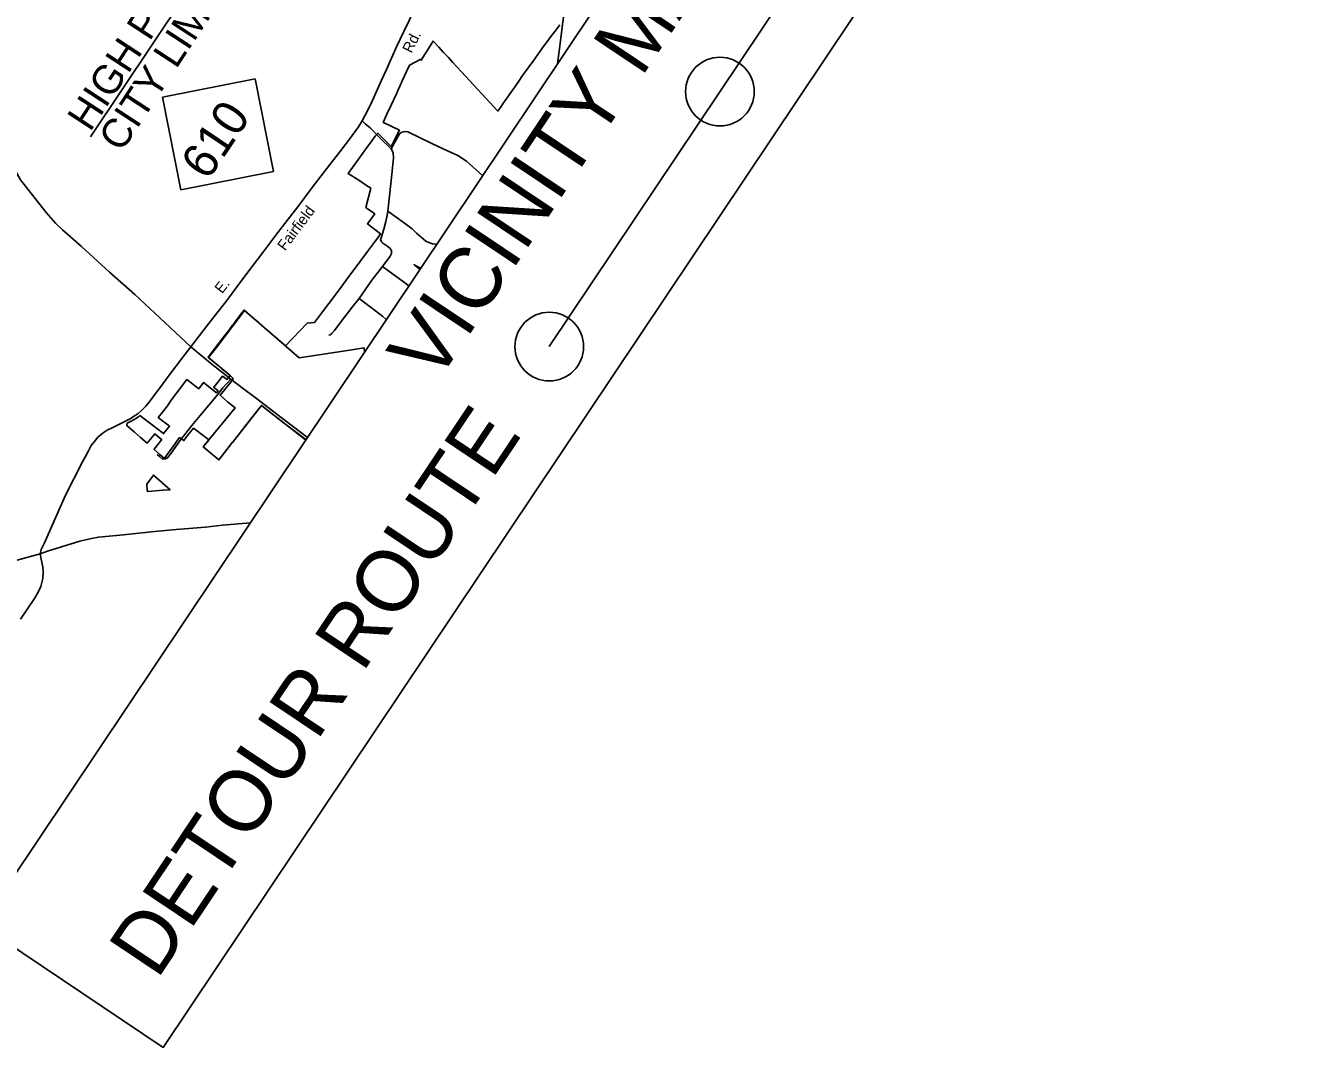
# Model space of a CAD drawing. Extents: x 1716282 to 1717158, y 799307 to 801078.
# Drawn here: x 1716655.2 to 1716967.1, y 800387.2 to 800636.9 of the extents above; entities that cross this region are included whole.
import ezdxf

# ---------------------------------------------------------------- set-up
doc = ezdxf.new("R2010")
doc.units = 0
for name, color, linetype in [('Exist Boundary Political City Limit New', 7, 'Continuous'), ('Exist Road Primary NC Attributed', 7, 'Continuous'), ('Exist Road Primary NC Label', 7, 'Continuous'), ('Exist Road Primary US UnDivided 4 Lane Attributed', 7, 'Continuous'), ('Exist Road Secondary Type 51 Attributed', 7, 'Continuous'), ('Map Preparation Boundary City Limit Buffer Line', 7, 'Continuous'), ('Old_Level_2', 7, 'Continuous'), ('Prop DSN Text', 7, 'Continuous')]:
    doc.layers.add(name, color=color, linetype=linetype)

msp = doc.modelspace()

# ---------------------------------------------------------------- linework, layer by layer
at = {"layer": 'Exist Boundary Political City Limit New'}
for points in [[(1716699.94, 800555.77), (1716699.83, 800555.86), (1716702.5, 800559.29), (1716703.08, 800560.05), (1716703.88, 800561.08), (1716704.85, 800562.33), (1716705.08, 800562.62), (1716705.85, 800563.67), (1716705.87, 800563.7), (1716707.14, 800565.38), (1716708.13, 800566.7), (1716708.65, 800567.4), (1716709.47, 800566.68), (1716710.49, 800565.8), (1716711.12, 800565.25), (1716712.01, 800564.49), (1716712.14, 800564.37), (1716712.3, 800564.24), (1716712.84, 800563.77), (1716713.66, 800563.06), (1716714.62, 800562.23), (1716715.44, 800561.52), (1716716.34, 800560.74), (1716718.23, 800559.11), (1716718.73, 800558.67), (1716724.09, 800564.21), (1716725.89, 800564.36), (1716727.8, 800566.92), (1716729.36, 800569.01), (1716730.63, 800570.72), (1716732.5, 800573.22), (1716734.02, 800575.26), (1716735.55, 800577.31), (1716738.85, 800581.74), (1716740.74, 800584.29), (1716741.31, 800585.07), (1716741.95, 800586.02), (1716738.81, 800588.44), (1716740.59, 800590.88), (1716739.7, 800591.53), (1716738.85, 800592.14), (1716738.42, 800592.46), (1716739.59, 800597.21), (1716739.26, 800597.43), (1716738.84, 800597.71), (1716736.92, 800598.95), (1716734.07, 800600.78), (1716735.54, 800602.81), (1716737.66, 800605.74), (1716738.93, 800607.48), (1716739.45, 800608.21), (1716740.71, 800609.92), (1716741.31, 800610.6), (1716744.62, 800607.4), (1716746.6, 800611.36), (1716742.71, 800613.22), (1716742.64, 800613.26), (1716743.55, 800615.24), (1716744.49, 800617.3), (1716745.86, 800620.27), (1716746.28, 800621.18), (1716746.77, 800622.25), (1716747.39, 800623.57), (1716747.87, 800624.61), (1716748.36, 800625.68), (1716749.07, 800627.21), (1716751.83, 800628.69), (1716751.94, 800628.47), (1716754.84, 800633.13), (1716756.22, 800631.64), (1716757.38, 800630.38), (1716758.57, 800629.1), (1716759.67, 800627.9), (1716760.76, 800626.72), (1716761.77, 800625.63), (1716770.65, 800616.01), (1716771.47, 800617.17), (1716771.89, 800617.77), (1716773.83, 800620.53), (1716774.46, 800621.43), (1716774.89, 800622.05), (1716775.93, 800623.57), (1716776.54, 800624.5), (1716776.94, 800625.06), (1716779.44, 800628.51), (1716781.61, 800631.51), (1716783.22, 800633.72), (1716783.89, 800634.6), (1716784.64, 800635.58), (1716785.58, 800636.8), (1716785.85, 800637.14)], [(1716751.75, 800577.61), (1716750.19, 800578.47), (1716751.6, 800577.38)], [(1716738.04, 800557.12), (1716737.99, 800558.13), (1716733.91, 800557.53), (1716722.1, 800555.73), (1716717.13, 800560.02), (1716708.72, 800567.3), (1716705.95, 800563.6), (1716701.87, 800558.28), (1716699.94, 800555.77)], [(1716699.94, 800555.77), (1716705.23, 800551.42), (1716706.01, 800550.66), (1716705.39, 800549.77), (1716703.17, 800547.06), (1716702.78, 800546.59), (1716704.57, 800544.99), (1716706.45, 800543.51), (1716700.04, 800535.64), (1716698.65, 800533.94), (1716702.48, 800530.78), (1716705.8, 800535.08), (1716705.83, 800535.05), (1716712.88, 800544.08), (1716723.69, 800535.68)], [(1716705.23, 800551.42), (1716703.33, 800552.96), (1716703.19, 800553.08), (1716701.52, 800554.48), (1716700.68, 800555.17), (1716700.06, 800555.68), (1716699.94, 800555.77)], [(1716700.04, 800535.64), (1716699.92, 800535.73), (1716698.98, 800536.46), (1716696.3, 800538.55), (1716694.82, 800536.71), (1716693.95, 800535.51), (1716692.87, 800536.23), (1716691.09, 800533.71), (1716690.05, 800532.32), (1716689.16, 800531.15), (1716688.16, 800532.02), (1716686.61, 800533.39), (1716686.63, 800533.41), (1716688.51, 800535.74), (1716688.41, 800535.82), (1716686.81, 800537.13), (1716684.92, 800534.86), (1716683.29, 800536.27), (1716681.86, 800537.52), (1716679.96, 800539.17), (1716679.96, 800539.2), (1716680.06, 800539.72), (1716681.05, 800540.23), (1716681.65, 800540.54), (1716681.95, 800540.73), (1716682.21, 800540.9), (1716682.83, 800541.29), (1716683.19, 800541.61), (1716684.56, 800540.58), (1716687.28, 800538.51), (1716688.98, 800537.22), (1716690.41, 800539.05), (1716690.32, 800539.12), (1716688.71, 800540.33), (1716687.66, 800541.12), (1716687.68, 800541.15), (1716688.72, 800542.45), (1716689.96, 800544), (1716690.79, 800545.4), (1716692.11, 800547.1), (1716694.67, 800550.42), (1716697.55, 800548.18), (1716698.72, 800549.67), (1716701.87, 800547.14), (1716702.31, 800547.66), (1716702.22, 800547.74), (1716701.2, 800548.54), (1716701.22, 800548.57), (1716701.95, 800549.47), (1716703.41, 800551.27), (1716704.49, 800550.45), (1716705.23, 800551.42)], [(1716723.73, 800535.74), (1716718.22, 800539.95), (1716712.88, 800544.08), (1716710.09, 800540.5), (1716705.83, 800535.05), (1716705.8, 800535.08), (1716702.86, 800531.28), (1716702.48, 800530.78), (1716698.65, 800533.94), (1716700.05, 800535.63), (1716700.04, 800535.64)]]:
    msp.add_lwpolyline(points, dxfattribs=at)
at = {"layer": 'Exist Road Primary NC Attributed'}
for points in [[(1716737.52, 800613.65), (1716738.97, 800616.41), (1716739.94, 800618.43), (1716742.26, 800623.58), (1716743.43, 800626.2), (1716745.92, 800631.71), (1716747.7, 800635.46), (1716749.03, 800638.19), (1716750.33, 800641.06), (1716751.44, 800643.48), (1716753.47, 800648.15), (1716754.71, 800651.24), (1716756.22, 800655.53), (1716757.28, 800658.48), (1716758.87, 800662.74)], [(1716785.21, 800627.6), (1716785.64, 800630.66), (1716786.55, 800637.79), (1716787.71, 800646.57), (1716788.09, 800649.32), (1716788.99, 800656.05)], [(1716695.67, 800558.39), (1716698.84, 800562.57), (1716701.69, 800566.26), (1716704.17, 800569.44), (1716708.36, 800575), (1716710.62, 800578.03), (1716713.2, 800581.43), (1716716.64, 800586.05), (1716719.45, 800589.64), (1716721.54, 800592.33), (1716725.32, 800597.34), (1716729.72, 800603.03), (1716732.08, 800606.06), (1716734.37, 800609.15), (1716736.6, 800612.2), (1716737.52, 800613.65)], [(1716658.79, 800507.85), (1716659.08, 800508.89), (1716659.83, 800510.47), (1716661.66, 800514.55), (1716665.01, 800522.12), (1716669.16, 800530.26), (1716669.95, 800531.76), (1716670.59, 800532.99), (1716671.28, 800534.27), (1716672.05, 800535.27), (1716672.92, 800536.3), (1716674.24, 800537.39), (1716675.18, 800538.01), (1716676.53, 800538.69), (1716678.68, 800539.75), (1716680.61, 800540.74), (1716682.04, 800541.6), (1716682.75, 800542.12), (1716683.68, 800542.95), (1716684.53, 800543.82), (1716685.42, 800544.88), (1716687.03, 800547.04), (1716687.87, 800548.15), (1716690.36, 800551.48), (1716693.66, 800555.91), (1716695.67, 800558.39)]]:
    msp.add_lwpolyline(points, dxfattribs=at)
at = {"layer": 'Exist Road Primary US UnDivided 4 Lane Attributed'}
for points in [[(1716710.12, 800515.41), (1716703.35, 800514.82), (1716699.22, 800514.37), (1716692.05, 800513.74), (1716685.93, 800513.17), (1716679.15, 800512.48), (1716673.04, 800511.91), (1716671.39, 800511.56), (1716668.5, 800510.9), (1716660.59, 800508.45), (1716658.79, 800507.85)], [(1716658.79, 800507.85), (1716634.94, 800501.26), (1716625.8, 800498.38), (1716621.59, 800497.24), (1716617.99, 800496.53), (1716616.31, 800496.29), (1716615.04, 800496.18), (1716614.04, 800496.37), (1716612.8, 800496.56), (1716611.7, 800496.82), (1716609.28, 800497.63), (1716605.06, 800499.1), (1716601.13, 800500.52), (1716594.98, 800502.8), (1716590.55, 800504.32), (1716583.68, 800506.84), (1716581.96, 800507.27), (1716580.45, 800507.4), (1716576.77, 800507.65)]]:
    msp.add_lwpolyline(points, dxfattribs=at)
at = {"layer": 'Exist Road Secondary Type 51 Attributed'}
for points in [[(1716695.67, 800558.39), (1716688.08, 800565.49), (1716681.92, 800571.19), (1716675.73, 800576.67), (1716668.88, 800582.96), (1716664.29, 800587.01), (1716662.56, 800588.64), (1716660.27, 800591.22), (1716653.98, 800599.21), (1716652.07, 800602.74), (1716650.94, 800604.38), (1716649.53, 800606.17), (1716648.03, 800607.76), (1716646.14, 800609.72), (1716642.26, 800612.96), (1716634.1, 800620.58), (1716631.07, 800624.03), (1716629.78, 800626.22), (1716628.69, 800628.46), (1716626.21, 800637.47), (1716625.41, 800641.76), (1716625.31, 800647.59), (1716627.05, 800656.51), (1716628.42, 800665.05)], [(1716737.52, 800613.65), (1716738.25, 800612.94), (1716739.43, 800611.92), (1716741.79, 800609.46), (1716744.6, 800606.8)], [(1716766.91, 800600.25), (1716763.03, 800603.81), (1716760.88, 800605.15), (1716758.36, 800606.31), (1716754.71, 800608.05), (1716748.65, 800610.93), (1716747.98, 800611.04), (1716747.2, 800610.88), (1716746.7, 800610.54), (1716746.31, 800609.86), (1716744.6, 800606.8)], [(1716744.6, 800606.8), (1716744.79, 800606.58), (1716745.1, 800605.82), (1716745.17, 800604.5), (1716744.6, 800599.09), (1716743.82, 800591.54)], [(1716743.82, 800591.54), (1716743.59, 800590.6), (1716743.26, 800589.05), (1716742.82, 800587.17), (1716742.13, 800585.05), (1716741.96, 800584.61), (1716742.11, 800584.2), (1716742.2, 800584.03), (1716742.52, 800583.71), (1716743.79, 800582.9), (1716744.43, 800582.32), (1716744.71, 800581.78), (1716744.67, 800581.2), (1716744.31, 800580.56), (1716742.5, 800578.01)], [(1716755.68, 800583.48), (1716754.73, 800583.58), (1716753.93, 800583.79), (1716753.07, 800584.22), (1716750.77, 800586.17), (1716749.76, 800587.21), (1716747.87, 800588.65), (1716743.82, 800591.54)], [(1716742.5, 800578.01), (1716739.9, 800574.67), (1716736.74, 800570.22)], [(1716742.5, 800578.01), (1716747.59, 800574.33), (1716748.9, 800573.35)], [(1716736.74, 800570.22), (1716735.03, 800568.08), (1716732.12, 800564.3), (1716730.77, 800562.42), (1716730.1, 800561.7), (1716729.67, 800561.33), (1716729.4, 800561.27)], [(1716736.74, 800570.22), (1716742.47, 800565.9), (1716743.38, 800565.11)], [(1716705.38, 800550.51), (1716700.42, 800554.41), (1716695.67, 800558.39)], [(1716705.38, 800550.51), (1716703.48, 800548.35), (1716702.14, 800546.67), (1716697.93, 800541.66), (1716695.85, 800539.14), (1716692.97, 800535.44), (1716690.81, 800532.43), (1716689.95, 800531.24), (1716689.45, 800531.03), (1716688.74, 800530.99), (1716687.95, 800531.6), (1716687.39, 800532.06)], [(1716724.09, 800536.29), (1716723.08, 800537.07), (1716718.07, 800540.91), (1716711.32, 800546.05), (1716708.51, 800548.17), (1716705.38, 800550.51)], [(1716654.04, 800491.83), (1716657.43, 800496.9), (1716658.39, 800498.59), (1716658.97, 800499.84), (1716659.47, 800501.75), (1716659.58, 800503.33), (1716659.48, 800504.6), (1716659.05, 800506.53), (1716658.79, 800507.85)]]:
    msp.add_lwpolyline(points, dxfattribs=at)
at = {"layer": 'Map Preparation Boundary City Limit Buffer Line'}
for points in [[(1716751.75, 800577.61), (1716750.19, 800578.47), (1716751.6, 800577.38)], [(1716688.9, 800523.34), (1716690.54, 800523.47), (1716690.43, 800523.57), (1716690.47, 800523.57), (1716686.47, 800527.04), (1716684.87, 800524.84), (1716684.99, 800523.41), (1716685.01, 800523.12), (1716685.02, 800523.02), (1716688.9, 800523.34)]]:
    msp.add_lwpolyline(points, dxfattribs=at)
at = {"layer": 'Old_Level_2'}
msp.add_lwpolyline([(1716693.2, 800596.81), (1716688.73, 800619.42), (1716711.33, 800623.9), (1716715.81, 800601.29)], close=True, dxfattribs=at)
at = {"layer": 'Prop DSN Text'}
for p, q in [((1716783.23, 800558.46), (1716866.67, 800683.12)), ((1716671.13, 800609.77), (1716705.74, 800661.48))]:
    msp.add_line(p, q, dxfattribs=at)
for points in [[(1716644.27, 800417.02), (1716922.46, 800832.66), (1716560.18, 801075.15), (1716281.98, 800659.5)], [(1716644.27, 800417.02), (1716922.46, 800832.66), (1716967.08, 800802.8), (1716688.88, 800387.16)]]:
    msp.add_lwpolyline(points, close=True, dxfattribs=at)
for centre in [(1716824.95, 800620.79), (1716783.23, 800558.46)]:
    msp.add_circle(centre, 8.4, dxfattribs=at)

# ---------------------------------------------------------------- texts
at = {"layer": 'Exist Road Primary NC Label'}
for s, rotation, p in [('Rd.', 62.7185, (1716749.52, 800630.01)), ('Fairfield', 53.0485, (1716718.65, 800581.71)), ('E.', 51.9649, (1716703.27, 800571.24))]:
    msp.add_text(s, height=2.61, rotation=rotation, dxfattribs=at).set_placement(p)
at = {"layer": 'Old_Level_2'}
msp.add_text('610', height=8.564, rotation=56.2051, dxfattribs=at).set_placement((1716699.82, 800598.81))
at = {"layer": 'Prop DSN Text'}
for s, height, rotation, p in [('VICINITY MAP', 15, 56.2051, (1716755.5, 800549.02)), ('HIGH POINT', 7.128, 56.7857, (1716671.02, 800610.75)), ('CITY LIMIT', 7.128, 56.7857, (1716678.67, 800605.73)), ('DETOUR ROUTE', 15, 56.2051, (1716687.39, 800403.53))]:
    msp.add_text(s, height=height, rotation=rotation, dxfattribs=at).set_placement(p)

doc.saveas('drawing.dxf')
